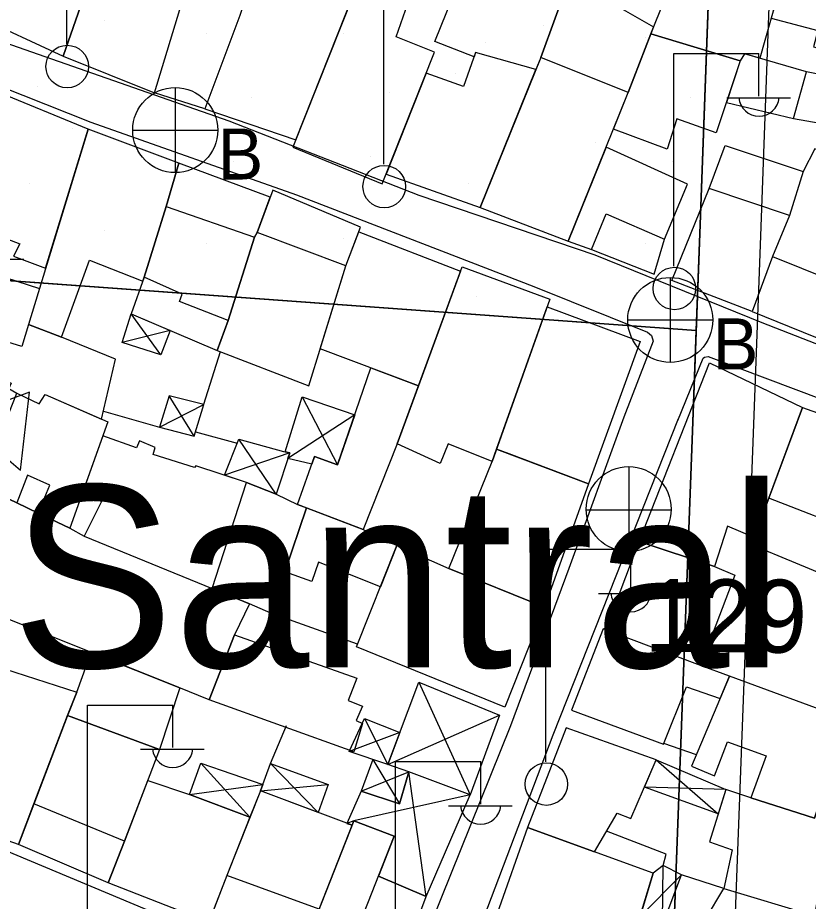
# Model space of a CAD drawing. Extents: x 417997 to 421451, y 4451742 to 4455216.
# Drawn here: x 419860.2 to 419925.3, y 4452433.3 to 4452506.1 of the extents above; entities that cross this region are included whole.
import ezdxf

# ---------------------------------------------------------------- set-up
doc = ezdxf.new("R2010")
doc.units = 0
for name, color, linetype in [('ADA', 7, 'Continuous'), ('B_Mesken', 7, 'Continuous'), ('B_Sundurma', 7, 'Continuous'), ('B_Teras', 7, 'Continuous'), ('Default', 7, 'Continuous'), ('KALDIRIM', 7, 'Continuous'), ('PL_REKRASYON', 7, 'Continuous'), ('PL_TİCK', 7, 'Continuous'), ('S_Elektrik_Diregi', 7, 'Continuous'), ('S_Rogar_Kapagi', 7, 'Continuous'), ('S_Rogar_Kapagi_Buski', 7, 'Continuous'), ('S_Trafo_acik_tip', 7, 'Continuous'), ('Sinir_Duvar_tek_tarafa_ait', 7, 'Continuous'), ('TR_PARKALANI', 7, 'Continuous'), ('TR_TİCK', 7, 'Continuous'), ('Y_Bucak_Koy', 7, 'Continuous'), ('Y_Kot_Noktasi', 7, 'Continuous'), ('Yol_Sose', 7, 'Continuous')]:
    doc.layers.add(name, color=color, linetype=linetype)

# ---------------------------------------------------------------- blocks, each defined once
blk = doc.blocks.new('POINT_DISPLAY')
at = {"layer": 'Default'}
blk.add_line((0, 0), (0, 0), dxfattribs=at)

msp = doc.modelspace()

# ---------------------------------------------------------------- linework, layer by layer
at = {"layer": 'ADA'}
for p, q in [((419918.101, 4452535.298), (419916.353, 4452488.301)), ((419918.101, 4452535.298), (419916.353, 4452488.301)), ((419916.353, 4452488.301), (419915.721, 4452471.309)), ((419916.353, 4452488.301), (419915.721, 4452471.309)), ((419851.01, 4452485.028), (419916.056, 4452480.305)), ((419851.01, 4452485.028), (419916.056, 4452480.305)), ((419915.721, 4452471.309), (419911.13, 4452347.859)), ((419915.721, 4452471.309), (419911.13, 4452347.859))]:
    msp.add_line(p, q, dxfattribs=at)
at = {"layer": 'B_Mesken'}
for points in [[(419878.496, 4452506.241), (419875.609, 4452498.569), (419871.473, 4452499.888), (419873.839, 4452507.663), (419875.987, 4452513.729), (419877.507, 4452518.723), (419882.438, 4452517.876), (419880.55, 4452512.408)], [(419863.948, 4452502.908), (419871.473, 4452499.888), (419873.839, 4452507.663), (419875.526, 4452512.428), (419871.13, 4452513.955), (419872.045, 4452517.303), (419869.327, 4452518.144), (419867.664, 4452513.558)], [(419856.721, 4452506.247), (419863.948, 4452502.908), (419867.664, 4452513.558), (419860.387, 4452516.34)], [(419912.316, 4452504.749), (419916.815, 4452515.857), (419924.397, 4452513.706), (419921.295, 4452502.726), (419920.028, 4452503.092), (419919.69, 4452502.517)], [(419922.227, 4452506.026), (419926.087, 4452505.022), (419925.712, 4452503.655), (419928.314, 4452502.945), (419927.866, 4452501.058), (419927.28, 4452499.115), (419930.412, 4452498.504), (419933.76, 4452510.961), (419933.859, 4452511.44), (419924.397, 4452513.706)], [(419882.863, 4452495.409), (419890.227, 4452492.372), (419894.534, 4452503.233), (419891.366, 4452504.483), (419893.862, 4452511.655), (419889.801, 4452512.896)], [(419897.776, 4452502.841), (419894.552, 4452504.118), (419898.029, 4452512.741), (419904.45, 4452509.774), (419905.629, 4452509.286), (419903.264, 4452502.789), (419902.861, 4452501.788), (419897.906, 4452503.202)], [(419875.609, 4452498.569), (419883.101, 4452496.011), (419887.913, 4452508.137), (419883.264, 4452510.602), (419882.259, 4452508.217), (419879.407, 4452508.974), (419878.496, 4452506.241)], [(419905.629, 4452509.286), (419912.545, 4452505.314), (419912.316, 4452504.749), (419910.468, 4452499.903), (419903.264, 4452502.789)], [(419910.468, 4452499.903), (419912.316, 4452504.749), (419919.69, 4452502.517), (419917.714, 4452496.588), (419914.478, 4452497.733), (419913.669, 4452495.251), (419909.247, 4452496.879)], [(419902.861, 4452501.788), (419897.906, 4452503.202), (419896.901, 4452500.401), (419893.846, 4452501.499), (419890.552, 4452493.191), (419898.291, 4452490.439)], [(419898.291, 4452490.439), (419905.532, 4452487.674), (419910.468, 4452499.903), (419903.264, 4452502.789)], [(419924.08, 4452497.77), (419926.734, 4452497.304), (419927.866, 4452501.058), (419925.131, 4452501.617), (419920.028, 4452503.092), (419919.69, 4452502.517), (419918.545, 4452499.081)], [(419866.027, 4452496.884), (419858.395, 4452500.018), (419854.97, 4452489.544), (419860.397, 4452487.455), (419859.873, 4452486.433), (419862.517, 4452485.439)], [(419873.48, 4452494.097), (419866.027, 4452496.884), (419861.095, 4452480.803), (419863.837, 4452479.749), (419866.139, 4452486.112), (419870.519, 4452484.384), (419870.633, 4452484.702), (419872.443, 4452490.513)], [(419922.335, 4452486.396), (419920.663, 4452481.885), (419914.057, 4452484.423), (419917.131, 4452492.011), (419918.436, 4452495.55), (419924.874, 4452493.407), (419923.73, 4452489.777)], [(419907.438, 4452486.972), (419912.61, 4452484.949), (419913.462, 4452487.826), (419915.338, 4452492.366), (419908.647, 4452495.391), (419905.532, 4452487.674)], [(419920.663, 4452481.885), (419927.899, 4452478.939), (419929.644, 4452483.466), (419933.076, 4452492.208), (419925.82, 4452495.278), (419924.874, 4452493.407), (419923.73, 4452489.777), (419922.335, 4452486.396)], [(419881.004, 4452491.276), (419873.48, 4452494.097), (419872.443, 4452490.513), (419870.633, 4452484.702), (419869.559, 4452481.689), (419876.639, 4452478.66), (419877.543, 4452481.146), (419879.718, 4452488.003), (419879.918, 4452488.365)], [(419887.221, 4452485.635), (419888.438, 4452488.826), (419881.22, 4452491.857), (419879.918, 4452488.365), (419879.718, 4452488.003), (419877.543, 4452481.146), (419876.639, 4452478.66), (419884.191, 4452475.767)], [(419888.288, 4452488.432), (419896.677, 4452485.206), (419893.197, 4452475.742), (419885.125, 4452478.809), (419887.221, 4452485.635)], [(419891.442, 4452470.966), (419896.803, 4452485.551), (419904.018, 4452482.883), (419899.283, 4452469.53), (419895.654, 4452470.967), (419894.986, 4452469.361)], [(419861.095, 4452480.803), (419860.558, 4452478.984), (419856.876, 4452480.121), (419858.243, 4452484.987), (419862.001, 4452483.756)], [(419903.795, 4452482.254), (419911.465, 4452479.392), (419907.207, 4452467.697), (419900.66, 4452470.157), (419899.637, 4452470.53)], [(419867.127, 4452473.017), (419868.266, 4452477.944), (419863.837, 4452479.749), (419861.095, 4452480.803), (419860.558, 4452478.984), (419856.876, 4452480.121), (419854.47, 4452481.209), (419853.396, 4452478.687), (419859.694, 4452475.983), (419859.487, 4452475.534), (419860.149, 4452475.159), (419861.981, 4452474.26), (419862.486, 4452475.033)], [(419891.442, 4452470.966), (419888.66, 4452463.934), (419883.258, 4452465.988), (419884.651, 4452469.946), (419886.545, 4452469.256), (419889.282, 4452477.23), (419893.197, 4452475.742)], [(419920.84, 4452463.261), (419918.627, 4452464.205), (419917.575, 4452460.887), (419911.376, 4452462.93), (419917.154, 4452477.655), (419924.815, 4452473.969)], [(419861.901, 4452465.283), (419860.138, 4452466.133), (419857.141, 4452467.55), (419860.149, 4452475.159), (419861.981, 4452474.26), (419862.486, 4452475.033), (419867.638, 4452472.795), (419864.519, 4452464.038)], [(419927.964, 4452459.616), (419920.554, 4452462.683), (419920.84, 4452463.261), (419922.039, 4452466.493), (419924.815, 4452473.969), (419932.534, 4452471.236), (419929.529, 4452463.594)], [(419865.553, 4452466.942), (419867.114, 4452466.22), (419865.689, 4452463.378), (419876.214, 4452459.078), (419879.048, 4452467.795), (419874.877, 4452469.17), (419874.779, 4452469.018), (419871.357, 4452470.092), (419871.529, 4452470.674), (419870.232, 4452471.218), (419869.988, 4452470.655), (419867.23, 4452471.65)], [(419895.71, 4452460.71), (419899.283, 4452469.53), (419899.637, 4452470.53), (419907.207, 4452467.697), (419903.586, 4452457.534)], [(419875.985, 4452449.9), (419873.49, 4452450.923), (419866.285, 4452453.791), (419858.539, 4452456.894), (419851.733, 4452459.387), (419851.316, 4452469.944), (419857.141, 4452467.55), (419860.138, 4452466.133), (419861.901, 4452465.283), (419864.519, 4452464.038), (419865.689, 4452463.378), (419876.214, 4452459.078), (419879.291, 4452457.798), (419878.076, 4452455.256)], [(419879.048, 4452467.795), (419881.5, 4452466.834), (419883.258, 4452465.988), (419883.992, 4452465.709), (419881.054, 4452457.049), (419879.291, 4452457.798), (419876.214, 4452459.078)], [(419888.66, 4452463.934), (419891.432, 4452462.609), (419890.068, 4452459.202), (419884.99, 4452461.23), (419884.434, 4452459.634), (419882.209, 4452460.453), (419883.992, 4452465.709)], [(419917.575, 4452460.887), (419919.252, 4452460.171), (419916.422, 4452452.717), (419908.631, 4452455.659), (419911.376, 4452462.93)], [(419903.586, 4452457.534), (419900.323, 4452449.291), (419888.096, 4452454.276), (419891.432, 4452462.609), (419895.71, 4452460.71)], [(419908.631, 4452455.659), (419908.419, 4452455.747), (419905.802, 4452449.055), (419913.376, 4452446.258), (419915.255, 4452450.97), (419918.032, 4452450.023), (419918.799, 4452451.849), (419916.422, 4452452.717)], [(419887.878, 4452445.618), (419875.985, 4452449.9), (419878.076, 4452455.256), (419888.131, 4452451.692), (419887.419, 4452449.846), (419888.591, 4452449.389), (419888.079, 4452448.187), (419888.606, 4452447.953)], [(419866.262, 4452453.8), (419873.554, 4452450.896), (419871.899, 4452445.821), (419864.325, 4452448.605), (419865.08, 4452450.537)], [(419860.286, 4452437.986), (419852.68, 4452440.668), (419857.415, 4452453.006), (419865.08, 4452450.537), (419864.297, 4452448.534)], [(419915.681, 4452444.43), (419917.57, 4452443.641), (419918.644, 4452446.45), (419921.828, 4452445.291), (419920.549, 4452441.845), (419925.801, 4452440.145), (419928.478, 4452448.292), (419918.799, 4452451.849)], [(419869, 4452438.265), (419867.677, 4452434.832), (419860.286, 4452437.986), (419861.557, 4452441.329), (419864.325, 4452448.605), (419871.899, 4452445.821)], [(419907.683, 4452437.382), (419909.562, 4452440.559), (419910.69, 4452440.13), (419912.775, 4452444.955), (419905.361, 4452447.59), (419902.183, 4452439.38)], [(419870.919, 4452443.266), (419874.358, 4452442.117), (419879.332, 4452440.238), (419877.419, 4452435.442), (419875.946, 4452431.583), (419867.677, 4452434.832), (419869, 4452438.265)], [(419887.738, 4452439.57), (419880.203, 4452442.421), (419877.419, 4452435.442), (419875.685, 4452430.898), (419883.122, 4452427.955), (419883.581, 4452428.988), (419885.029, 4452432.674)], [(419920.549, 4452441.845), (419918.49, 4452442.516), (419917.162, 4452438.198), (419919.033, 4452437.54), (419918.331, 4452434.363), (419925.832, 4452432.114), (419927.185, 4452440.314), (419925.997, 4452440.742), (419925.801, 4452440.145)], [(419887.024, 4452428.05), (419891.085, 4452426.364), (419893.835, 4452433.709), (419889.908, 4452435.386), (419891.2, 4452438.674), (419887.879, 4452439.929), (419883.581, 4452428.988), (419886.866, 4452427.649)], [(419910.351, 4452428.503), (419912.529, 4452435.622), (419902.183, 4452439.38), (419899.679, 4452432.296)], [(419920.863, 4452424.615), (419917.374, 4452426.008), (419915.462, 4452426.687), (419916.593, 4452429.325), (419914.28, 4452429.999), (419915.062, 4452432.416), (419916.818, 4452431.855), (419918.331, 4452434.363), (419925.832, 4452432.114), (419925.804, 4452426.853), (419923.767, 4452426.069)]]:
    msp.add_lwpolyline(points, close=True, dxfattribs=at)
at = {"layer": 'B_Sundurma'}
for p, q in [((419872.001, 4452478.304), (419869.559, 4452481.689)), ((419872.755, 4452480.322), (419868.823, 4452479.316)), ((419874.754, 4452471.6), (419872.673, 4452474.939)), ((419883.632, 4452474.839), (419886.545, 4452469.256)), ((419871.892, 4452472.358), (419875.551, 4452474.21)), ((419887.957, 4452473.37), (419882.465, 4452469.783)), ((419881.5, 4452466.834), (419878.409, 4452471.366)), ((419882.615, 4452470.241), (419877.238, 4452468.392)), ((419893.243, 4452451.346), (419897.459, 4452442.085)), ((419888.762, 4452448.365), (419890.677, 4452444.564)), ((419890.677, 4452444.564), (419899.877, 4452448.631)), ((419891.684, 4452447.224), (419887.509, 4452445.639)), ((419875.283, 4452444.689), (419879.332, 4452440.238)), ((419881.03, 4452444.652), (419884.938, 4452440.63)), ((419889.437, 4452444.984), (419891.652, 4452441.343)), ((419912.775, 4452444.955), (419917.874, 4452440.515)), ((419888.501, 4452442.384), (419892.422, 4452443.973)), ((419893.835, 4452433.709), (419892.422, 4452443.973)), ((419874.358, 4452442.117), (419880.387, 4452442.919)), ((419880.203, 4452442.421), (419885.781, 4452442.917)), ((419918.49, 4452442.516), (419911.809, 4452442.72)), ((419897.459, 4452442.085), (419887.879, 4452439.929)), ((419887.879, 4452439.929), (419887.318, 4452439.73)), ((419913.277, 4452431.353), (419913.34, 4452436.266)), ((419914.867, 4452435.488), (419911.44, 4452432.062))]:
    msp.add_line(p, q, dxfattribs=at)
for points in [[(419872.755, 4452480.322), (419872.001, 4452478.304), (419868.823, 4452479.316), (419869.559, 4452481.689)], [(419871.892, 4452472.358), (419874.754, 4452471.6), (419875.551, 4452474.21), (419872.673, 4452474.939)], [(419882.22, 4452470.331), (419883.632, 4452474.839), (419887.957, 4452473.37), (419886.545, 4452469.256), (419884.651, 4452469.946), (419884.424, 4452469.299), (419882.465, 4452469.783), (419882.615, 4452470.241)], [(419882.615, 4452470.241), (419881.5, 4452466.834), (419879.048, 4452467.795), (419877.238, 4452468.392), (419878.409, 4452471.366), (419882.094, 4452470.359)], [(419892.422, 4452443.973), (419890.677, 4452444.564), (419893.243, 4452451.346), (419899.877, 4452448.631), (419897.459, 4452442.085)], [(419888.762, 4452448.365), (419891.684, 4452447.224), (419890.677, 4452444.564), (419887.509, 4452445.639)], [(419874.358, 4452442.117), (419875.283, 4452444.689), (419880.387, 4452442.919), (419880.203, 4452442.421), (419879.332, 4452440.238)], [(419880.203, 4452442.421), (419881.03, 4452444.652), (419885.781, 4452442.917), (419884.938, 4452440.63)], [(419889.437, 4452444.984), (419888.501, 4452442.384), (419891.652, 4452441.343), (419892.422, 4452443.973), (419890.677, 4452444.564)], [(419912.775, 4452444.955), (419918.49, 4452442.516), (419917.874, 4452440.515), (419911.809, 4452442.72)], [(419893.835, 4452433.709), (419897.459, 4452442.085), (419892.422, 4452443.973), (419891.652, 4452441.343), (419888.501, 4452442.384), (419887.318, 4452439.73), (419887.738, 4452439.57), (419887.879, 4452439.929), (419891.2, 4452438.674), (419889.908, 4452435.386)], [(419913.277, 4452431.353), (419914.867, 4452435.488), (419913.34, 4452436.266), (419912.529, 4452435.622), (419911.44, 4452432.062)]]:
    msp.add_lwpolyline(points, close=True, dxfattribs=at)
at = {"layer": 'B_Teras'}
for points in [[(419918.545, 4452499.081), (419924.08, 4452497.77), (419925.131, 4452501.617), (419920.028, 4452503.092), (419919.69, 4452502.517)], [(419917.131, 4452492.011), (419918.436, 4452495.55), (419924.874, 4452493.407), (419923.73, 4452489.777)], [(419905.532, 4452487.674), (419907.438, 4452486.972), (419908.648, 4452489.903), (419913.462, 4452487.826), (419915.338, 4452492.366), (419908.647, 4452495.391)], [(419923.73, 4452489.777), (419922.335, 4452486.396), (419929.644, 4452483.466), (419933.076, 4452492.208), (419925.82, 4452495.278), (419924.874, 4452493.407)], [(419870.633, 4452484.702), (419872.443, 4452490.513), (419879.718, 4452488.003), (419877.543, 4452481.146), (419873.536, 4452482.71), (419873.766, 4452483.288)], [(419877.543, 4452481.146), (419876.639, 4452478.66), (419884.191, 4452475.767), (419887.221, 4452485.635), (419879.918, 4452488.365), (419879.718, 4452488.003)], [(419860.149, 4452475.159), (419861.981, 4452474.26), (419862.486, 4452475.033), (419867.638, 4452472.795), (419864.519, 4452464.038), (419861.901, 4452465.283), (419862.876, 4452467.57), (419861.025, 4452468.398), (419860.138, 4452466.133), (419857.141, 4452467.55)], [(419924.815, 4452473.969), (419932.534, 4452471.236), (419929.529, 4452463.594), (419922.039, 4452466.493)], [(419861.557, 4452441.329), (419864.325, 4452448.605), (419871.899, 4452445.821), (419869, 4452438.265)], [(419883.581, 4452428.988), (419886.866, 4452427.649), (419891.2, 4452438.674), (419887.879, 4452439.929)], [(419885.029, 4452432.674), (419877.419, 4452435.442), (419875.685, 4452430.898), (419883.122, 4452427.955), (419883.581, 4452428.988)]]:
    msp.add_lwpolyline(points, close=True, dxfattribs=at)
at = {"layer": 'KALDIRIM'}
for p, q in [((419923.098, 4452535.112), (419921.35, 4452488.116)), ((419923.098, 4452535.112), (419921.35, 4452488.116)), ((419921.35, 4452488.116), (419920.718, 4452471.123)), ((419921.35, 4452488.116), (419920.718, 4452471.123)), ((419920.718, 4452471.123), (419915.858, 4452340.467)), ((419920.718, 4452471.123), (419915.858, 4452340.467))]:
    msp.add_line(p, q, dxfattribs=at)
at = {"layer": 'PL_REKRASYON'}
msp.add_lwpolyline([(419851.01, 4452485.028), (419916.056, 4452480.305), (419916.353, 4452488.301), (419917.525, 4452519.802), (419843.661, 4452525.165), (419845.038, 4452517.777), (419849.022, 4452496.397), (419850.208, 4452490.029)], dxfattribs=at)
msp.add_lwpolyline([(419851.01, 4452485.028), (419916.056, 4452480.305), (419916.353, 4452488.301), (419917.525, 4452519.802), (419843.661, 4452525.165), (419845.038, 4452517.777), (419849.022, 4452496.397), (419850.208, 4452490.029)], dxfattribs=at)
at = {"layer": 'PL_TİCK'}
msp.add_lwpolyline([(419845.37, 4452436.166), (419842.015, 4452427.344), (419818.489, 4452365.48), (419824.841, 4452354.764), (419905.991, 4452343.547), (419911.13, 4452347.859), (419915.721, 4452471.309), (419916.056, 4452480.305), (419851.01, 4452485.028)], dxfattribs=at)
msp.add_lwpolyline([(419845.37, 4452436.166), (419842.015, 4452427.344), (419818.489, 4452365.48), (419824.841, 4452354.764), (419905.991, 4452343.547), (419911.13, 4452347.859), (419915.721, 4452471.309), (419916.056, 4452480.305), (419851.01, 4452485.028)], dxfattribs=at)
at = {"layer": 'S_Elektrik_Diregi'}
for p, q in [((419864.261, 4452503.877), (419864.261, 4452521.377)), ((419890.349, 4452493.993), (419890.349, 4452511.493)), ((419914.232, 4452485.604), (419914.232, 4452503.104)), ((419914.232, 4452503.104), (419921.232, 4452503.104)), ((419921.232, 4452499.604), (419921.232, 4452503.104)), ((419918.572, 4452499.464), (419923.822, 4452499.464)), ((419855.461, 4452486.184), (419860.711, 4452486.184)), ((419903.693, 4452444.799), (419903.693, 4452462.299)), ((419903.693, 4452462.299), (419910.693, 4452462.299)), ((419910.693, 4452458.799), (419910.693, 4452462.299)), ((419908.033, 4452458.659), (419913.283, 4452458.659)), ((419865.976, 4452431.974), (419865.976, 4452449.474)), ((419865.976, 4452449.474), (419872.976, 4452449.474)), ((419872.976, 4452445.974), (419872.976, 4452449.474)), ((419870.316, 4452445.834), (419875.566, 4452445.834)), ((419891.324, 4452427.312), (419891.324, 4452444.812)), ((419891.324, 4452444.812), (419898.324, 4452444.812)), ((419898.324, 4452441.312), (419898.324, 4452444.812)), ((419895.664, 4452441.172), (419900.914, 4452441.172))]:
    msp.add_line(p, q, dxfattribs=at)
for centre in [(419864.297, 4452502.042), (419890.385, 4452492.158), (419914.268, 4452483.768), (419903.729, 4452442.964)]:
    msp.add_circle(centre, 1.75, dxfattribs=at)
for centre in [(419921.233, 4452499.617), (419910.694, 4452458.812), (419872.977, 4452445.987), (419898.325, 4452441.325)]:
    msp.add_arc(centre, 1.658, 184.83843, 355.14641, dxfattribs=at)
at = {"layer": 'S_Rogar_Kapagi'}
for p, q in [((419910.558, 4452462.072), (419910.558, 4452469.072)), ((419906.988, 4452465.537), (419913.988, 4452465.537))]:
    msp.add_line(p, q, dxfattribs=at)
msp.add_circle((419910.505, 4452465.6), 3.5, dxfattribs=at)
at = {"layer": 'S_Rogar_Kapagi_Buski'}
for p, q in [((419873.182, 4452500.306), (419873.182, 4452493.306)), ((419869.682, 4452496.806), (419876.682, 4452496.806)), ((419913.932, 4452484.676), (419913.932, 4452477.676)), ((419910.432, 4452481.176), (419917.432, 4452481.176))]:
    msp.add_line(p, q, dxfattribs=at)
for centre in [(419873.182, 4452496.806), (419913.932, 4452481.176)]:
    msp.add_circle(centre, 3.5, dxfattribs=at)
at = {"layer": 'S_Trafo_acik_tip'}
msp.add_lwpolyline([(419860.46, 4452468.814), (419861.195, 4452475.219), (419855.42, 4452473.084)], close=True, dxfattribs=at)
at = {"layer": 'Sinir_Duvar_tek_tarafa_ait'}
for points in [[(419876.886, 4452478.565), (419875.525, 4452474.216)], [(419867.28, 4452473.677), (419871.892, 4452472.358)], [(419874.862, 4452471.954), (419878.282, 4452471.043)], [(419888.176, 4452454.477), (419881.054, 4452457.049)], [(419881.03, 4452444.652), (419882.335, 4452447.791)], [(419916.077, 4452445.373), (419913.394, 4452446.303)], [(419913.34, 4452436.266), (419913.582, 4452437.207), (419908.694, 4452439.091)], [(419918.331, 4452434.363), (419914.867, 4452435.488)]]:
    msp.add_lwpolyline(points, dxfattribs=at)
at = {"layer": 'TR_TİCK'}
for points in [[(419916.056, 4452480.305), (419851.01, 4452485.028)], [(419916.056, 4452480.305), (419851.01, 4452485.028)], [(419845.37, 4452436.166), (419842.015, 4452427.344), (419818.489, 4452365.48), (419824.841, 4452354.764), (419905.991, 4452343.547), (419911.13, 4452347.859), (419915.721, 4452471.309), (419916.056, 4452480.305)], [(419845.37, 4452436.166), (419842.015, 4452427.344), (419818.489, 4452365.48), (419824.841, 4452354.764), (419905.991, 4452343.547), (419911.13, 4452347.859), (419915.721, 4452471.309), (419916.056, 4452480.305)]]:
    msp.add_lwpolyline(points, dxfattribs=at)
at = {"layer": 'Yol_Sose'}
for points in [[(419939.215, 4452474.037), (419921.495, 4452480.933), (419907.739, 4452486.51), (419893.257, 4452491.438), (419877.616, 4452497.551), (419857.435, 4452504.586), (419846.076, 4452508.751), (419840.7, 4452510.93), (419838.791, 4452511.943), (419836.66, 4452514.816)], [(419841.467, 4452506.404), (419851.424, 4452503.342), (419866.231, 4452497.457), (419883.171, 4452491.475), (419902.706, 4452483.924), (419912.06, 4452480.164), (419912.39, 4452479.892), (419912.517, 4452479.432), (419910.102, 4452473.177), (419905.58, 4452460.702), (419900.791, 4452447.751), (419891.756, 4452425.346)], [(419879.1, 4452429.142), (419849.673, 4452441.481), (419846.6, 4452442.896), (419846.012, 4452443.215), (419845.62, 4452443.84), (419845.645, 4452444.595), (419848.694, 4452452.376), (419851.069, 4452459.696), (419850.554, 4452468.942), (419849.476, 4452480.076), (419846.715, 4452486.24), (419841.249, 4452500.95), (419839.956, 4452504.23), (419839.983, 4452505.013), (419840.222, 4452505.491), (419840.532, 4452505.963), (419840.904, 4452506.271)], [(419914.541, 4452472.896), (419916.625, 4452478.029), (419916.748, 4452478.122), (419917.056, 4452478.158), (419936.146, 4452470.967), (419955.59, 4452463.228), (419972.442, 4452456.447), (419972.781, 4452456.117), (419972.961, 4452455.581), (419972.594, 4452454.113), (419967.588, 4452441.903), (419960.402, 4452425.437), (419954.813, 4452409.959), (419954.352, 4452407.38), (419953.046, 4452400.331)], [(419953.046, 4452400.331), (419950.664, 4452384.578), (419949.679, 4452376.533), (419949.589, 4452376.09), (419949.269, 4452375.895), (419948.582, 4452375.843), (419934.617, 4452377.494), (419921.086, 4452379.113), (419920.683, 4452379.375), (419914.193, 4452391.605), (419904.313, 4452408.842), (419895.714, 4452423.272), (419895.664, 4452423.595), (419895.724, 4452424.419), (419904.295, 4452447.012), (419914.614, 4452473.075)]]:
    msp.add_lwpolyline(points, dxfattribs=at)

# ---------------------------------------------------------------- block references
at = {"layer": 'TR_PARKALANI', "xscale": 0.1, "yscale": 0.10000000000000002}
for p in [(419867.356, 4452505.826), (419867.356, 4452505.826), (419903.459, 4452505.449), (419903.459, 4452505.449), (419875.781, 4452504.778), (419875.781, 4452504.778), (419887.063, 4452504.778), (419887.063, 4452504.778), (419911.884, 4452504.402), (419911.884, 4452504.402), (419898.697, 4452504.055), (419898.697, 4452504.055), (419896.214, 4452501.496), (419896.214, 4452501.496), (419861.857, 4452500.381), (419861.857, 4452500.381), (419890.785, 4452499.897), (419890.785, 4452499.897), (419879.503, 4452499.521), (419879.503, 4452499.521), (419915.605, 4452499.521), (419915.605, 4452499.521), (419864.73, 4452496.916), (419864.73, 4452496.916), (419900.833, 4452496.916), (419900.833, 4452496.916), (419871.637, 4452495.791), (419871.637, 4452495.791), (419907.739, 4452495.791), (419907.739, 4452495.791), (419877.984, 4452494.234), (419877.984, 4452494.234), (419889.266, 4452494.61), (419889.266, 4452494.61), (419914.086, 4452494.234), (419914.086, 4452494.234), (419861.218, 4452492.399), (419861.218, 4452492.399), (419897.32, 4452492.399), (419897.32, 4452492.399), (419867.356, 4452488.526), (419867.356, 4452488.526), (419903.459, 4452488.526), (419903.459, 4452488.526), (419875.781, 4452487.479), (419875.781, 4452487.479), (419887.063, 4452487.855), (419887.063, 4452487.855), (419911.884, 4452487.479), (419911.884, 4452487.479), (419862.18, 4452485.137), (419862.18, 4452485.137), (419863.926, 4452484.022), (419863.926, 4452484.022), (419896.214, 4452484.197), (419896.214, 4452484.197), (419878.505, 4452483.122), (419878.505, 4452483.122), (419897.96, 4452483.082), (419897.96, 4452483.082), (419910.983, 4452483.215), (419910.983, 4452483.215), (419887.063, 4452482.59), (419887.063, 4452482.59)]:
    msp.add_blockref('POINT_DISPLAY', p, dxfattribs=at)

# ---------------------------------------------------------------- texts
at = {"layer": 'S_Rogar_Kapagi_Buski'}
for p in [(419876.682, 4452492.741), (419917.432, 4452477.111)]:
    msp.add_text('B', height=4.2, dxfattribs=at).set_placement(p)
at = {"layer": 'Y_Bucak_Koy'}
msp.add_text('Santral Garaj', height=15, dxfattribs=at).set_placement((419859.693, 4452452.568))
at = {"layer": 'Y_Kot_Noktasi'}
msp.add_text('129.79 ', height=6, rotation=359.61735, dxfattribs=at).set_placement((419911.792, 4452453.86))

doc.saveas('drawing.dxf')
